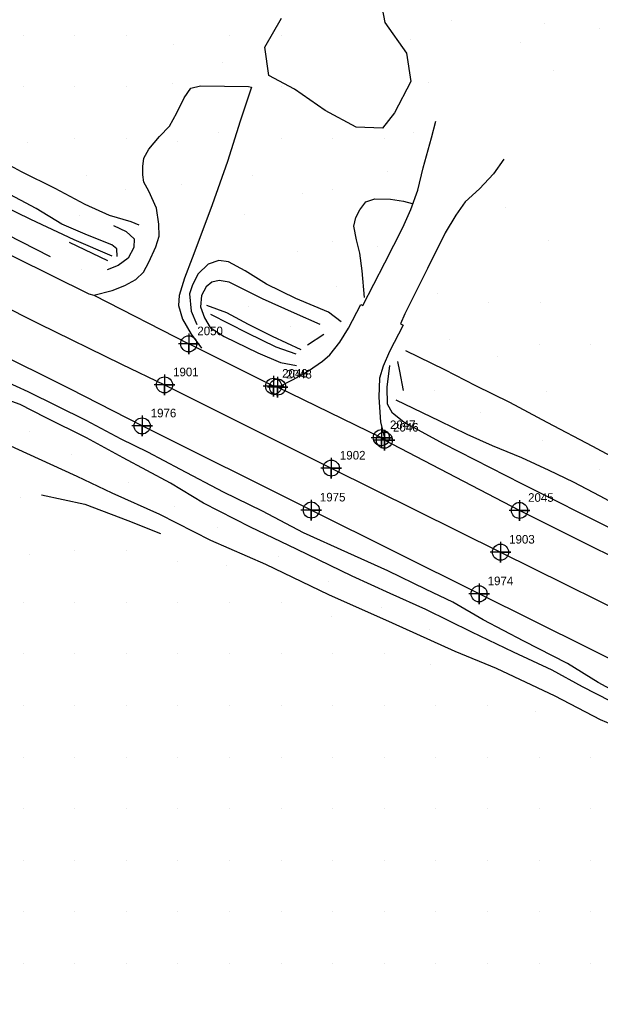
# Model space of a CAD drawing. Extents: x 1497074 to 1501343, y 481943 to 486114.
# Drawn here: x 1499353.3 to 1499522.1, y 482804.6 to 483091.2 of the extents above; entities that cross this region are included whole.
import ezdxf

# ---------------------------------------------------------------- set-up
doc = ezdxf.new("R2010")
doc.units = 0
for name, color, linetype in [('Exist DTM Crownline', 7, 'Continuous'), ('Exist DTM Crownline Cogo Number', 7, 'Continuous'), ('Exist DTM Crownline Cogo Point CELL', 7, 'Continuous'), ('Exist Roads EOP', 7, 'Continuous'), ('Exist Roads EOP Cogo Number', 7, 'Continuous'), ('Exist Roads EOP Cogo Point CELL', 7, 'Continuous'), ('PH Exist DTM Breakline', 7, 'Continuous'), ('PH Exist DTM Obscure Area', 7, 'Continuous'), ('PH Exist DTM Point', 7, 'Continuous')]:
    doc.layers.add(name, color=color, linetype=linetype)

msp = doc.modelspace()

# ---------------------------------------------------------------- linework, layer by layer
at = {"layer": 'Exist DTM Crownline'}
msp.add_lwpolyline([(1499395.36, 482985.01), (1499443.87, 482960.81), (1499493.08, 482936.36), (1499540.5, 482912.88), (1499586.46, 482890.36), (1499633.9, 482867.41), (1499680.88, 482845.25), (1499726.12, 482824.18), (1499773.19, 482803.77), (1499819.04, 482785.34), (1499906.6, 482751.56), (1499930.69, 482742.84), (1499979.87, 482724.77), (1500026.26, 482708.17), (1500077.15, 482689.67), (1500127.52, 482671.55), (1500177.68, 482653.78), (1500231.5, 482634.52), (1500279.65, 482617.19), (1500328.73, 482599.71), (1500369.66, 482584.94)], dxfattribs=at)
at = {"layer": 'Exist DTM Crownline Cogo Point CELL'}
for points in [[(1499395.36, 482988.01), (1499395.36, 482982.01), (1499395.36, 482985.01), (1499398.36, 482985.01), (1499392.36, 482985.01)], [(1499443.87, 482963.81), (1499443.87, 482957.81), (1499443.87, 482960.81), (1499446.87, 482960.81), (1499440.87, 482960.81)], [(1499493.08, 482939.36), (1499493.08, 482933.36), (1499493.08, 482936.36), (1499496.08, 482936.36), (1499490.08, 482936.36)]]:
    msp.add_lwpolyline(points, dxfattribs=at)
for centre in [(1499395.36, 482985.01), (1499443.87, 482960.81), (1499493.08, 482936.36)]:
    msp.add_circle(centre, 2.34, dxfattribs=at)
at = {"layer": 'Exist Roads EOP'}
for points in [[(1499731.6, 482836.87), (1499686.89, 482857.05), (1499639.8, 482879.21), (1499592.33, 482902.29), (1499546.33, 482924.68), (1499498.59, 482948.51), (1499459.31, 482968.94), (1499458.43, 482969.66), (1499428.27, 482984.38), (1499427.08, 482984.62), (1499402.41, 482996.96)], [(1499698.51, 482821.61), (1499675.14, 482832.32), (1499627.94, 482855.07), (1499580.83, 482877.79), (1499534.68, 482900.49), (1499486.84, 482924.26), (1499438.05, 482948.62), (1499388.86, 482973.08)]]:
    msp.add_lwpolyline(points, dxfattribs=at)
at = {"layer": 'Exist Roads EOP Cogo Point CELL'}
for points in [[(1499402.41, 482999.96), (1499402.41, 482993.96), (1499402.41, 482996.96), (1499405.41, 482996.96), (1499399.41, 482996.96)], [(1499427.08, 482987.62), (1499427.08, 482981.62), (1499427.08, 482984.62), (1499430.08, 482984.62), (1499424.08, 482984.62)], [(1499428.27, 482987.38), (1499428.27, 482981.38), (1499428.27, 482984.38), (1499431.27, 482984.38), (1499425.27, 482984.38)], [(1499388.86, 482976.08), (1499388.86, 482970.08), (1499388.86, 482973.08), (1499391.86, 482973.08), (1499385.86, 482973.08)], [(1499458.43, 482972.66), (1499458.43, 482966.66), (1499458.43, 482969.66), (1499461.43, 482969.66), (1499455.43, 482969.66)], [(1499459.31, 482971.94), (1499459.31, 482965.94), (1499459.31, 482968.94), (1499462.31, 482968.94), (1499456.31, 482968.94)], [(1499438.05, 482951.62), (1499438.05, 482945.62), (1499438.05, 482948.62), (1499441.05, 482948.62), (1499435.05, 482948.62)], [(1499498.59, 482951.51), (1499498.59, 482945.51), (1499498.59, 482948.51), (1499501.59, 482948.51), (1499495.59, 482948.51)], [(1499486.84, 482927.26), (1499486.84, 482921.26), (1499486.84, 482924.26), (1499489.84, 482924.26), (1499483.84, 482924.26)]]:
    msp.add_lwpolyline(points, dxfattribs=at)
for centre in [(1499402.41, 482996.96), (1499427.08, 482984.62), (1499428.27, 482984.38), (1499388.86, 482973.08), (1499458.43, 482969.66), (1499459.31, 482968.94), (1499438.05, 482948.62), (1499498.59, 482948.51), (1499486.84, 482924.26)]:
    msp.add_circle(centre, 2.34, dxfattribs=at)
at = {"layer": 'PH Exist DTM Breakline'}
for points in [[(1499264.62, 483091.08), (1499282.11, 483081.78), (1499299.52, 483073.03), (1499310.06, 483067.99), (1499320.44, 483063.44), (1499328.59, 483059.47), (1499335.45, 483056.82), (1499343.99, 483052.28), (1499353.66, 483047.06), (1499363.49, 483042.26), (1499372.25, 483037.61), (1499379.31, 483034.35), (1499385.59, 483032.57), (1499387.91, 483031.54)], [(1499380.12, 483022.43), (1499369.07, 483027.2), (1499356.49, 483033.12), (1499344.27, 483039.02), (1499334.16, 483044.05), (1499321.83, 483050.09), (1499311.82, 483055.41), (1499300.85, 483060.67), (1499289.61, 483066.64), (1499280.36, 483070.81), (1499261.92, 483080.13)], [(1499381.6, 483022.36), (1499381.55, 483024.55), (1499380.04, 483025.77), (1499372.95, 483028.55), (1499365.51, 483031.75), (1499358.01, 483036.31), (1499348.93, 483041.14), (1499339.42, 483046.3), (1499330.45, 483050.84), (1499320.22, 483056.27), (1499313.59, 483060.41), (1499307.33, 483063.74), (1499300.22, 483066.41), (1499291.67, 483070.9), (1499282.03, 483075.45)], [(1499250.66, 483073.18), (1499280.3, 483058.22), (1499305.81, 483045.22), (1499327.76, 483034.22), (1499351.86, 483022.15), (1499373.34, 483011.53), (1499374.78, 483011.07), (1499402.41, 482996.96)], [(1499259.84, 483074.22), (1499267.4, 483069.31), (1499282.54, 483061.82), (1499297.77, 483054.41), (1499311.32, 483048.03), (1499328.15, 483039.93), (1499345.2, 483030.97), (1499362.08, 483022.33)], [(1499374.78, 483011.07), (1499380.16, 483012.49), (1499383.79, 483013.93), (1499387.06, 483015.67), (1499389.24, 483017.8), (1499390.77, 483020.68), (1499392.81, 483025.13), (1499393.79, 483028.29), (1499393.69, 483031.74), (1499393, 483036.39), (1499390.77, 483041.37), (1499389.4, 483043.94), (1499389.02, 483046.11), (1499389.06, 483048.55), (1499389.36, 483051), (1499390.83, 483053.53), (1499393.88, 483057.3), (1499396.78, 483060.29), (1499399, 483064.17), (1499401.13, 483068.55), (1499403, 483071.32), (1499405.84, 483071.99), (1499419.79, 483071.79), (1499420.63, 483071.64), (1499417.35, 483061.69), (1499413.66, 483049.97), (1499409.22, 483037.38), (1499405.89, 483028.53), (1499403.38, 483021.92), (1499401.22, 483016.08), (1499399.62, 483011.03), (1499399.46, 483008.08), (1499400.56, 483004.13), (1499403.12, 482999.72), (1499406.14, 482995.74)], [(1499243.67, 483061.67), (1499270.12, 483048.37), (1499307.12, 483029), (1499335.38, 483014.56), (1499358.7, 483002.86), (1499382.84, 482991), (1499395.36, 482985.01)], [(1499428.6, 482984.44), (1499432.82, 482986.63), (1499437.28, 482989.11), (1499441.32, 482991.92), (1499443.47, 482993.8), (1499446.39, 482997.47), (1499448.83, 483001.51), (1499452.48, 483008.38), (1499453.04, 483008.08), (1499459.48, 483020.54), (1499464.63, 483030.76), (1499467.01, 483035.98), (1499469.05, 483041.69), (1499470.55, 483048.16), (1499473.02, 483056.85), (1499474.31, 483061.71)], [(1499494.08, 483050.66), (1499491.04, 483046.4), (1499486.93, 483042.02), (1499482.84, 483038.22), (1499480.04, 483034.38), (1499476.93, 483029.21), (1499471.88, 483018.91), (1499465.28, 483005.66), (1499464.01, 483002.79), (1499464.76, 483002.39), (1499460.77, 482994.77), (1499458.93, 482990.45), (1499457.89, 482986.96), (1499457.73, 482981.4), (1499458.21, 482974.18), (1499459.43, 482969.26)], [(1499388.86, 482973.08), (1499367.82, 482983.86), (1499344.59, 482995.36), (1499321.43, 483006.9), (1499299.54, 483018.19), (1499295.2, 483020.39), (1499293.98, 483020.29), (1499273.88, 483030.3), (1499255.94, 483039.57), (1499252.82, 483036.35)], [(1499453.53, 483010.48), (1499452.8, 483018.21), (1499452.17, 483023.32), (1499451.17, 483027.25), (1499450.41, 483031.15), (1499450.97, 483033.7), (1499452.14, 483035.89), (1499453.9, 483038.24), (1499456.55, 483039.14), (1499461.05, 483039.07), (1499464.89, 483038.45), (1499467.43, 483037.79)], [(1499380.58, 483031.4), (1499384.25, 483029.66), (1499386.53, 483027.54), (1499386.48, 483025.02), (1499384.8, 483021.87), (1499381.89, 483019.7), (1499378.65, 483018.45)], [(1499378.91, 483021.11), (1499367.77, 483026.45)], [(1499446.72, 483003.31), (1499443.01, 483006.13), (1499433.56, 483010.11), (1499425.06, 483014.31), (1499418.79, 483018.22), (1499413.97, 483020.78), (1499411.2, 483021.22), (1499408.06, 483020.12), (1499405.15, 483017.32), (1499403.47, 483014.16), (1499402.59, 483011.46), (1499403.12, 483006.43), (1499404.8, 483002.62)], [(1499440.66, 483002.57), (1499433.16, 483005.85), (1499423.89, 483010.06), (1499414.13, 483014.91), (1499411.25, 483015.38), (1499409.15, 483014.93), (1499407.47, 483013.57), (1499406.14, 483011.02), (1499405.87, 483007.68), (1499406.97, 483004.51), (1499408.68, 483001.66), (1499412.69, 482999.07), (1499422.54, 482994.34), (1499429.07, 482991.48), (1499433.71, 482990.66)], [(1499435.12, 482995.19), (1499426.79, 482999.12), (1499419.75, 483002.58), (1499413.53, 483005.94), (1499407.7, 483008.12)], [(1499408.74, 483005.54), (1499419.39, 483000.13), (1499427.76, 482996.07), (1499433.57, 482994.05)], [(1499436.98, 482996.62), (1499441.67, 482999.79)], [(1499569.38, 482939.45), (1499555.59, 482945.83), (1499544.06, 482952.45), (1499533.12, 482960.03), (1499519.92, 482967.05), (1499506.63, 482974.11), (1499495.82, 482979.85), (1499485.92, 482984.72), (1499476.91, 482989.41), (1499465.54, 482994.89)], [(1499464.84, 482983.35), (1499463.75, 482989.03), (1499463.26, 482991.84)], [(1499554.47, 482928.86), (1499526.35, 482942.7), (1499499.25, 482956.26), (1499476.52, 482967.92), (1499464.94, 482974.18), (1499461.69, 482976.81), (1499460.19, 482979.45), (1499460.13, 482984.35), (1499460.87, 482990.61)], [(1499531.84, 482892.85), (1499521.45, 482898.49), (1499512.58, 482903.98), (1499499.86, 482910.46), (1499487.99, 482916.64), (1499479.25, 482921.85), (1499471.5, 482925.48), (1499460.32, 482930.95), (1499448.67, 482936.16), (1499435.81, 482941.98), (1499423.89, 482948.31), (1499412.5, 482953.79), (1499400.01, 482960.42), (1499390.51, 482965.44), (1499382.74, 482969.27), (1499372.58, 482974.7), (1499364.12, 482978.83), (1499355.7, 482982.98), (1499348.93, 482986.12)], [(1499525.07, 482893.07), (1499516.9, 482897.23), (1499508.08, 482902.08), (1499496.84, 482907.26), (1499484.71, 482913.1), (1499471.4, 482919.73), (1499461.02, 482924.34), (1499449.95, 482929.39), (1499433.75, 482937.25), (1499420.4, 482943.62), (1499406.68, 482950.59), (1499397.07, 482956.39), (1499383.39, 482963.78), (1499372.71, 482969.59), (1499360.77, 482975.57), (1499353.39, 482979.36), (1499348.54, 482981.1)], [(1499559.95, 482933), (1499547.84, 482939.44), (1499538.16, 482944.09), (1499529.39, 482948.65), (1499522.08, 482952.68), (1499514.27, 482956.74), (1499507.24, 482960.1), (1499499.29, 482963.79), (1499490.71, 482967.25), (1499483.35, 482970.57), (1499475.46, 482974.49), (1499462.75, 482980.59)], [(1499339.96, 482972.14), (1499355.23, 482965.11), (1499369.9, 482958.45), (1499380.09, 482953.58), (1499393.87, 482947.39), (1499408.71, 482939.89), (1499424.74, 482932.88), (1499443.1, 482924.02), (1499461.53, 482915.83), (1499479.74, 482907.55), (1499491.77, 482902.64), (1499508.84, 482894.62), (1499522.01, 482887.72), (1499536.81, 482881.48), (1499553, 482872.55), (1499563.99, 482866.65), (1499578.21, 482860.08), (1499601.81, 482849.91), (1499618.96, 482841.56), (1499639.41, 482832.09), (1499662.39, 482822.9), (1499678.74, 482815.76), (1499696.7, 482807.4)], [(1499359.6, 482953.04), (1499372.18, 482950.28), (1499384.68, 482945.58), (1499394.21, 482941.83)]]:
    msp.add_lwpolyline(points, dxfattribs=at)
at = {"layer": 'PH Exist DTM Obscure Area'}
msp.add_lwpolyline([(1499456.97, 483103.19), (1499459.45, 483090.38), (1499465.7, 483081.47), (1499467.03, 483073.26), (1499462.21, 483064.15), (1499458.73, 483059.71), (1499451.13, 483059.98), (1499442.06, 483064.81), (1499433.15, 483071.06), (1499425.74, 483075.04), (1499424.54, 483083.2), (1499429.4, 483091.71)], dxfattribs=at)
at = {"layer": 'PH Exist DTM Point'}
for p, q in [((1499478.92, 483090.93), (1499478.92, 483090.93)), ((1499505.75, 483090.16), (1499505.75, 483090.16)), ((1499354.29, 483086.76), (1499354.29, 483086.76)), ((1499369.29, 483086.76), (1499369.29, 483086.76)), ((1499384.29, 483086.76), (1499384.29, 483086.76)), ((1499414.29, 483086.76), (1499414.29, 483086.76)), ((1499429.29, 483086.76), (1499429.29, 483086.76)), ((1499521.9, 483088.56), (1499521.9, 483088.56)), ((1499397.89, 483084.14), (1499397.89, 483084.14)), ((1499467, 483085.43), (1499467, 483085.43)), ((1499498.75, 483084.74), (1499498.75, 483084.74)), ((1499412.12, 483078.78), (1499412.12, 483078.78)), ((1499508.57, 483076.48), (1499508.57, 483076.48)), ((1499354.29, 483071.76), (1499354.29, 483071.76)), ((1499369.29, 483071.76), (1499369.29, 483071.76)), ((1499384.29, 483071.76), (1499384.29, 483071.76)), ((1499397.62, 483072.64), (1499397.62, 483072.64)), ((1499429.29, 483071.76), (1499429.29, 483071.76)), ((1499472.1, 483072.92), (1499472.1, 483072.92)), ((1499411.16, 483058.42), (1499411.16, 483058.42)), ((1499467.74, 483058.38), (1499467.74, 483058.38)), ((1499355.66, 483055.39), (1499355.66, 483055.39)), ((1499369.29, 483056.76), (1499369.29, 483056.76)), ((1499384.29, 483056.76), (1499384.29, 483056.76)), ((1499399.2, 483055.93), (1499399.2, 483055.93)), ((1499429.29, 483056.76), (1499429.29, 483056.76)), ((1499444.29, 483056.76), (1499444.29, 483056.76)), ((1499459.29, 483056.76), (1499459.29, 483056.76)), ((1499372.72, 483046.04), (1499372.72, 483046.04)), ((1499420.94, 483045.79), (1499420.94, 483045.79)), ((1499460.18, 483047.16), (1499460.18, 483047.16)), ((1499400.19, 483043.2), (1499400.19, 483043.2)), ((1499384.03, 483041.9), (1499384.03, 483041.9)), ((1499435.63, 483040.68), (1499435.63, 483040.68)), ((1499444.29, 483041.76), (1499444.29, 483041.76)), ((1499418.63, 483034.7), (1499418.63, 483034.7)), ((1499494.55, 483036.66), (1499494.55, 483036.66)), ((1499370.74, 483034.25), (1499370.74, 483034.25)), ((1499444.14, 483026.84), (1499444.14, 483026.84)), ((1499507.09, 483027.1), (1499507.09, 483027.1)), ((1499434.13, 483023.95), (1499434.13, 483023.95)), ((1499457.16, 483025.25), (1499457.16, 483025.25)), ((1499371.22, 483018.67), (1499371.22, 483018.67)), ((1499445.26, 483013.64), (1499445.26, 483013.64)), ((1499474.81, 483011.48), (1499474.81, 483011.48)), ((1499489.58, 483009.08), (1499489.58, 483009.08)), ((1499504.76, 483009.01), (1499504.76, 483009.01)), ((1499419.86, 483007.75), (1499419.86, 483007.75)), ((1499432, 483001.87), (1499432, 483001.87)), ((1499478.1, 482998.33), (1499478.1, 482998.33)), ((1499504.29, 482996.76), (1499504.29, 482996.76)), ((1499519.29, 482996.76), (1499519.29, 482996.76)), ((1499492.1, 482993.26), (1499492.1, 482993.26)), ((1499473.84, 482983.47), (1499473.84, 482983.47)), ((1499506.3, 482982.99), (1499506.3, 482982.99)), ((1499487.2, 482976.97), (1499487.2, 482976.97)), ((1499356.17, 482971.38), (1499356.17, 482971.38)), ((1499505.27, 482968.95), (1499505.27, 482968.95)), ((1499368.22, 482964.66), (1499368.22, 482964.66)), ((1499521.83, 482960.43), (1499521.83, 482960.43)), ((1499384.79, 482956.6), (1499384.79, 482956.6)), ((1499353.46, 482952.2), (1499353.46, 482952.2)), ((1499398.2, 482949.71), (1499398.2, 482949.71)), ((1499410.83, 482943.52), (1499410.83, 482943.52)), ((1499356.23, 482935.73), (1499356.23, 482935.73)), ((1499369.29, 482936.76), (1499369.29, 482936.76)), ((1499384.29, 482936.76), (1499384.29, 482936.76)), ((1499428.42, 482935.13), (1499428.42, 482935.13)), ((1499399.01, 482933.73), (1499399.01, 482933.73)), ((1499413.3, 482932.49), (1499413.3, 482932.49)), ((1499442.91, 482927.71), (1499442.91, 482927.71)), ((1499354.29, 482921.76), (1499354.29, 482921.76)), ((1499369.29, 482921.76), (1499369.29, 482921.76)), ((1499384.29, 482921.76), (1499384.29, 482921.76)), ((1499399.29, 482921.76), (1499399.29, 482921.76)), ((1499414.29, 482921.76), (1499414.29, 482921.76)), ((1499429.29, 482921.76), (1499429.29, 482921.76)), ((1499458.49, 482920.27), (1499458.49, 482920.27)), ((1499443.94, 482917.55), (1499443.94, 482917.55)), ((1499472.51, 482913.79), (1499472.51, 482913.79)), ((1499354.29, 482906.76), (1499354.29, 482906.76)), ((1499369.29, 482906.76), (1499369.29, 482906.76)), ((1499384.29, 482906.76), (1499384.29, 482906.76)), ((1499399.29, 482906.76), (1499399.29, 482906.76)), ((1499414.29, 482906.76), (1499414.29, 482906.76)), ((1499429.29, 482906.76), (1499429.29, 482906.76)), ((1499444.29, 482906.76), (1499444.29, 482906.76)), ((1499459.29, 482906.76), (1499459.29, 482906.76)), ((1499472.7, 482903.77), (1499472.7, 482903.77)), ((1499354.29, 482891.76), (1499354.29, 482891.76)), ((1499369.29, 482891.76), (1499369.29, 482891.76)), ((1499384.29, 482891.76), (1499384.29, 482891.76)), ((1499399.29, 482891.76), (1499399.29, 482891.76)), ((1499414.29, 482891.76), (1499414.29, 482891.76)), ((1499429.29, 482891.76), (1499429.29, 482891.76)), ((1499444.29, 482891.76), (1499444.29, 482891.76)), ((1499459.29, 482891.76), (1499459.29, 482891.76)), ((1499474.29, 482891.76), (1499474.29, 482891.76)), ((1499489.29, 482891.76), (1499489.29, 482891.76)), ((1499503.31, 482889.93), (1499503.31, 482889.93)), ((1499354.29, 482876.76), (1499354.29, 482876.76)), ((1499369.29, 482876.76), (1499369.29, 482876.76)), ((1499384.29, 482876.76), (1499384.29, 482876.76)), ((1499399.29, 482876.76), (1499399.29, 482876.76)), ((1499414.29, 482876.76), (1499414.29, 482876.76)), ((1499429.29, 482876.76), (1499429.29, 482876.76)), ((1499444.29, 482876.76), (1499444.29, 482876.76)), ((1499459.29, 482876.76), (1499459.29, 482876.76)), ((1499474.29, 482876.76), (1499474.29, 482876.76)), ((1499489.29, 482876.76), (1499489.29, 482876.76)), ((1499504.29, 482876.76), (1499504.29, 482876.76)), ((1499519.29, 482876.76), (1499519.29, 482876.76)), ((1499354.29, 482861.76), (1499354.29, 482861.76)), ((1499369.29, 482861.76), (1499369.29, 482861.76)), ((1499384.29, 482861.76), (1499384.29, 482861.76)), ((1499399.29, 482861.76), (1499399.29, 482861.76)), ((1499414.29, 482861.76), (1499414.29, 482861.76)), ((1499429.29, 482861.76), (1499429.29, 482861.76)), ((1499444.29, 482861.76), (1499444.29, 482861.76)), ((1499459.29, 482861.76), (1499459.29, 482861.76)), ((1499474.29, 482861.76), (1499474.29, 482861.76)), ((1499489.29, 482861.76), (1499489.29, 482861.76)), ((1499504.29, 482861.76), (1499504.29, 482861.76)), ((1499519.29, 482861.76), (1499519.29, 482861.76)), ((1499354.29, 482846.76), (1499354.29, 482846.76)), ((1499369.29, 482846.76), (1499369.29, 482846.76)), ((1499384.29, 482846.76), (1499384.29, 482846.76)), ((1499399.29, 482846.76), (1499399.29, 482846.76)), ((1499414.29, 482846.76), (1499414.29, 482846.76)), ((1499429.29, 482846.76), (1499429.29, 482846.76)), ((1499444.29, 482846.76), (1499444.29, 482846.76)), ((1499459.29, 482846.76), (1499459.29, 482846.76)), ((1499474.29, 482846.76), (1499474.29, 482846.76)), ((1499489.29, 482846.76), (1499489.29, 482846.76)), ((1499504.29, 482846.76), (1499504.29, 482846.76)), ((1499519.29, 482846.76), (1499519.29, 482846.76)), ((1499354.29, 482831.76), (1499354.29, 482831.76)), ((1499369.29, 482831.76), (1499369.29, 482831.76)), ((1499384.29, 482831.76), (1499384.29, 482831.76)), ((1499399.29, 482831.76), (1499399.29, 482831.76)), ((1499414.29, 482831.76), (1499414.29, 482831.76)), ((1499429.29, 482831.76), (1499429.29, 482831.76)), ((1499444.29, 482831.76), (1499444.29, 482831.76)), ((1499459.29, 482831.76), (1499459.29, 482831.76)), ((1499474.29, 482831.76), (1499474.29, 482831.76)), ((1499489.29, 482831.76), (1499489.29, 482831.76)), ((1499504.29, 482831.76), (1499504.29, 482831.76)), ((1499519.29, 482831.76), (1499519.29, 482831.76)), ((1499354.29, 482816.76), (1499354.29, 482816.76)), ((1499369.29, 482816.76), (1499369.29, 482816.76)), ((1499384.29, 482816.76), (1499384.29, 482816.76)), ((1499399.29, 482816.76), (1499399.29, 482816.76)), ((1499414.29, 482816.76), (1499414.29, 482816.76)), ((1499429.29, 482816.76), (1499429.29, 482816.76)), ((1499444.29, 482816.76), (1499444.29, 482816.76)), ((1499459.29, 482816.76), (1499459.29, 482816.76)), ((1499474.29, 482816.76), (1499474.29, 482816.76)), ((1499489.29, 482816.76), (1499489.29, 482816.76)), ((1499504.29, 482816.76), (1499504.29, 482816.76)), ((1499519.29, 482816.76), (1499519.29, 482816.76))]:
    msp.add_line(p, q, dxfattribs=at)

# ---------------------------------------------------------------- texts
at = {"layer": 'Exist DTM Crownline Cogo Number'}
for s, p in [('1901', (1499397.86, 482987.52)), ('1902', (1499446.37, 482963.31)), ('1903', (1499495.58, 482938.86))]:
    msp.add_text(s, height=2.5, dxfattribs=at).set_placement(p)
at = {"layer": 'Exist Roads EOP Cogo Number'}
for s, p in [('2050', (1499404.91, 482999.46)), ('2049', (1499429.58, 482987.12)), ('2048', (1499430.77, 482986.88)), ('1976', (1499391.36, 482975.58)), ('2047', (1499460.93, 482972.16)), ('2046', (1499461.81, 482971.44)), ('1975', (1499440.55, 482951.12)), ('2045', (1499501.09, 482951.01)), ('1974', (1499489.34, 482926.76))]:
    msp.add_text(s, height=2.5, dxfattribs=at).set_placement(p)

doc.saveas('drawing.dxf')
